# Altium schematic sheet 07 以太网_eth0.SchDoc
size 297 x 209 mm
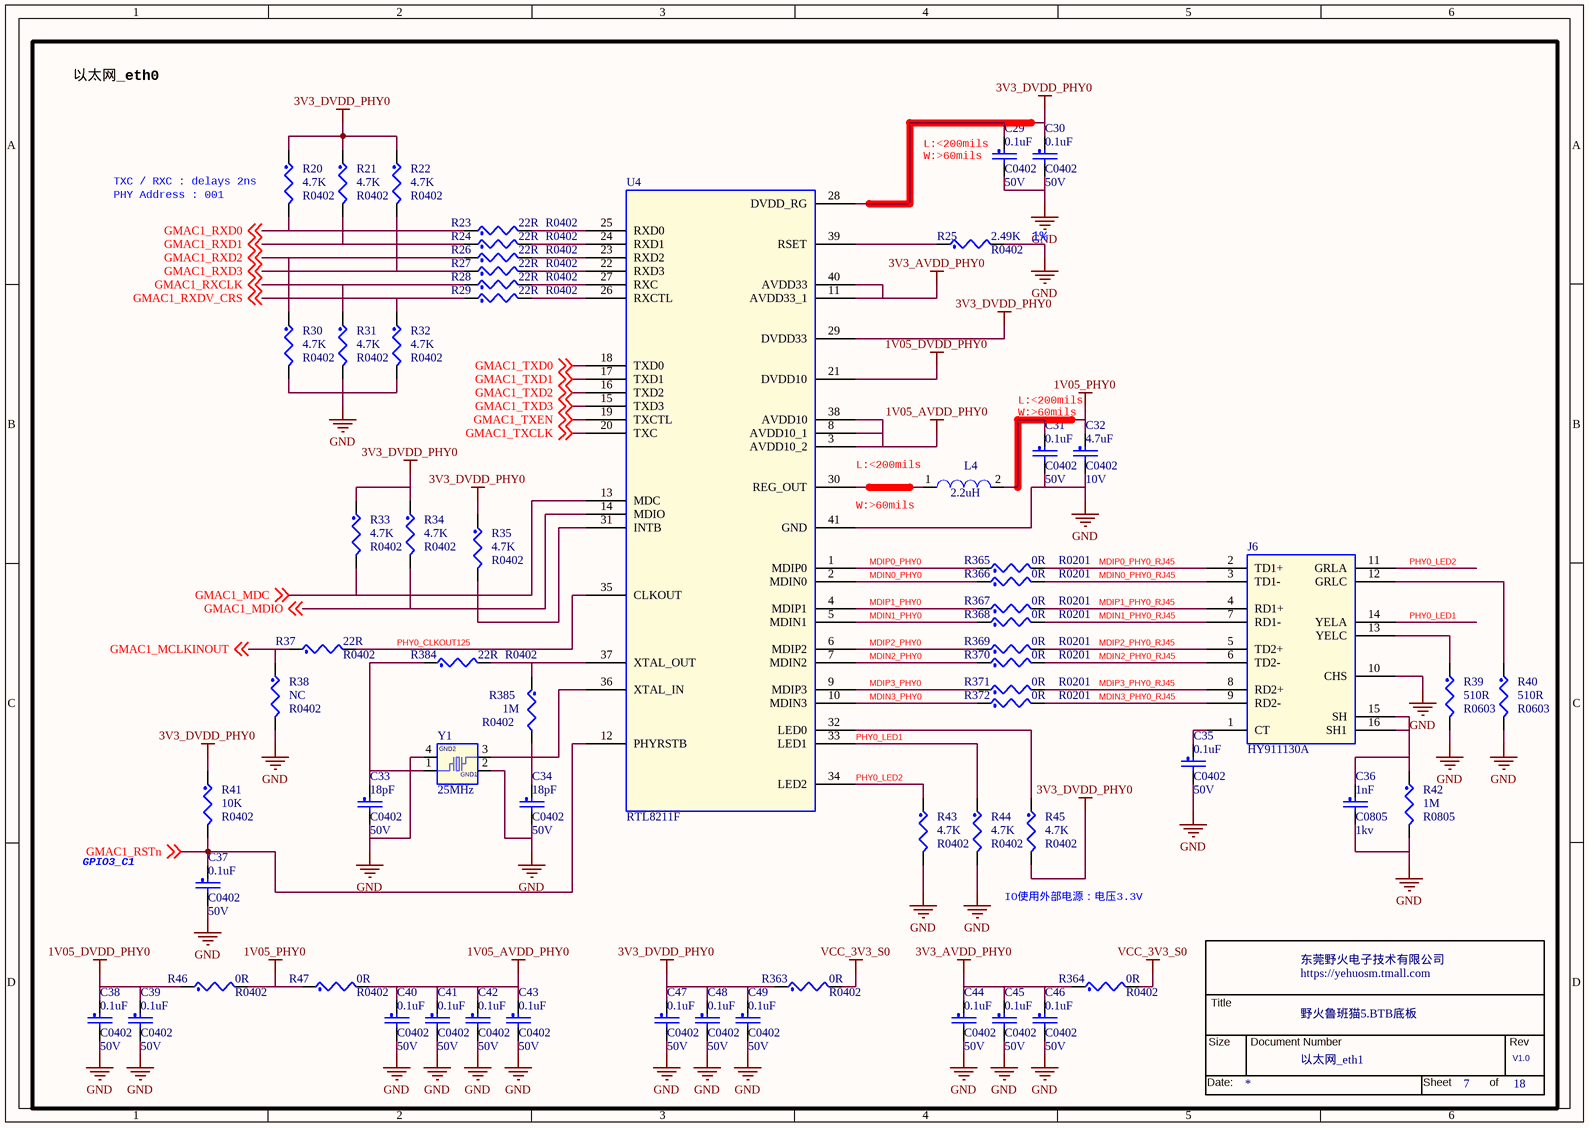
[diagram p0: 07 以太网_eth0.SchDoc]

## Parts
*  Doc: 以太网_eth1  RevCode: V1.0  Title: 野火鲁班猫5.BTB底板  OrgName: 东莞野火电子技术有限公司  Page Number: 7  Page Count: 18  (hidden comment: TitleBlock_YHSCH)  (graphical)
C29  0.1uF  Voltage: 50V  [C0402]
C30  0.1uF  Voltage: 50V  [C0402]
C31  0.1uF  Voltage: 50V  [C0402]
C32  4.7uF  Voltage: 10V  [C0402]
C33  18pF  Voltage: 50V  [C0402]
C34  18pF  Voltage: 50V  [C0402]
C35  0.1uF  Voltage: 50V  [C0402]
C36  1nF  Voltage: 1kv  [C0805]
C37  0.1uF  Voltage: 50V  [C0402]
C38  0.1uF  Voltage: 50V  [C0402]
C39  0.1uF  Voltage: 50V  [C0402]
C40  0.1uF  Voltage: 50V  [C0402]
C41  0.1uF  Voltage: 50V  [C0402]
C42  0.1uF  Voltage: 50V  [C0402]
C43  0.1uF  Voltage: 50V  [C0402]
C44  0.1uF  Voltage: 50V  [C0402]
C45  0.1uF  Voltage: 50V  [C0402]
C46  0.1uF  Voltage: 50V  [C0402]
C47  0.1uF  Voltage: 50V  [C0402]
C48  0.1uF  Voltage: 50V  [C0402]
C49  0.1uF  Voltage: 50V  [C0402]
J6  HY911130A  [HY911130A]
L4  2.2uH  [L2520]
R20  4.7K  [R0402]
R21  4.7K  [R0402]
R22  4.7K  [R0402]
R23  22R  [R0402]
R24  22R  [R0402]
R25  2.49K  [R0402]
R26  22R  [R0402]
R27  22R  [R0402]
R28  22R  [R0402]
R29  22R  [R0402]
R30  4.7K  [R0402]
R31  4.7K  [R0402]
R32  4.7K  [R0402]
R33  4.7K  [R0402]
R34  4.7K  [R0402]
R35  4.7K  [R0402]
R37  22R  [R0402]
R38  NC  [R0402]
R39  510R  [R0603]
R40  510R  [R0603]
R41  10K  [R0402]
R42  1M  [R0805]
R43  4.7K  [R0402]
R44  4.7K  [R0402]
R45  4.7K  [R0402]
R46  0R  [R0402]
R47  0R  [R0402]
R363  0R  [R0402]
R364  0R  [R0402]
R365  0R  [R0201]
R366  0R  [R0201]
R367  0R  [R0201]
R368  0R  [R0201]
R369  0R  [R0201]
R370  0R  [R0201]
R371  0R  [R0201]
R372  0R  [R0201]
R384  22R  [R0402]
R385  1M  [R0402]
U4  RTL8211F  [qfp_40p_r]
Y1  25MHz  [3225]

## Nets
1V05_AVDD_PHY0: C40.1 C41.1 C42.1 C43.1 R47.2 U4.3(AVDD10_2) U4.8(AVDD10_1) U4.38(AVDD10)
1V05_DVDD_PHY0: C38.1 C39.1 R46.1 U4.21(DVDD10)
1V05_PHY0: C31.1 C32.1 L4.2 R46.2 R47.1
3V3_AVDD_PHY0: C44.1 C45.1 C46.1 R364.1 U4.11(AVDD33_1) U4.40(AVDD33)
3V3_DVDD_PHY0: C29.1 C30.1 C47.1 C48.1 C49.1 R20.1 R21.1 R22.1 R33.1 R34.1 R35.1 R41.1 R45.2 R363.1 U4.28(DVDD_RG) U4.29(DVDD33)
GND: C29.2 C30.2 C31.2 C32.2 C33.2 C34.2 C35.2 C36.2 C37.2 C38.2 C39.2 C40.2 C41.2 C42.2 C43.2 C44.2 C45.2 C46.2 C47.2 C48.2 C49.2 J6.10(CHS) R25.2 R30.2 R31.2 R32.2 R38.2 R39.2 R40.2 R42.2 R43.2 R44.2 U4.41(GND) Y1.2(GND1) Y1.4(GND2)
VCC_3V3_S0: R363.2 R364.2
GMAC1_MCLKINOUT: R37.1 R38.1 ; off-sheet GMAC1_MCLKINOUT
GMAC1_MDC: R33.2 U4.13(MDC) ; off-sheet GMAC1_MDC
GMAC1_MDIO: R34.2 U4.14(MDIO) ; off-sheet GMAC1_MDIO
GMAC1_RSTn: C37.1 R41.2 U4.12(PHYRSTB) ; off-sheet GMAC1_RSTn
GMAC1_RXCLK: R28.1 R31.1 ; off-sheet GMAC1_RXCLK
GMAC1_RXD0: R20.2 R23.1 ; off-sheet GMAC1_RXD0
GMAC1_RXD1: R21.2 R24.1 ; off-sheet GMAC1_RXD1
GMAC1_RXD2: R26.1 R30.1 ; off-sheet GMAC1_RXD2
GMAC1_RXD3: R22.2 R27.1 ; off-sheet GMAC1_RXD3
GMAC1_RXDV_CRS: R29.1 R32.1 ; off-sheet GMAC1_RXDV_CRS
GMAC1_TXCLK: U4.20(TXC) ; off-sheet GMAC1_TXCLK
GMAC1_TXD0: U4.18(TXD0) ; off-sheet GMAC1_TXD0
GMAC1_TXD1: U4.17(TXD1) ; off-sheet GMAC1_TXD1
GMAC1_TXD2: U4.16(TXD2) ; off-sheet GMAC1_TXD2
GMAC1_TXD3: U4.15(TXD3) ; off-sheet GMAC1_TXD3
GMAC1_TXEN: U4.19(TXCTL) ; off-sheet GMAC1_TXEN
MDIN0_PHY0: R366.1 U4.2(MDIN0)
MDIN0_PHY0_RJ45: J6.3(TD1-) R366.2
MDIN1_PHY0: R368.1 U4.5(MDIN1)
MDIN1_PHY0_RJ45: J6.7(RD1-) R368.2
MDIN2_PHY0: R370.1 U4.7(MDIN2)
MDIN2_PHY0_RJ45: J6.6(TD2-) R370.2
MDIN3_PHY0: R372.1 U4.10(MDIN3)
MDIN3_PHY0_RJ45: J6.9(RD2-) R372.2
MDIP0_PHY0: R365.1 U4.1(MDIP0)
MDIP0_PHY0_RJ45: J6.2(TD1+) R365.2
MDIP1_PHY0: R367.1 U4.4(MDIP1)
MDIP1_PHY0_RJ45: J6.4(RD1+) R367.2
MDIP2_PHY0: R369.1 U4.6(MDIP2)
MDIP2_PHY0_RJ45: J6.5(TD2+) R369.2
MDIP3_PHY0: R371.1 U4.9(MDIP3)
MDIP3_PHY0_RJ45: J6.8(RD2+) R371.2
PHY0_CLKOUT125: R37.2 U4.35(CLKOUT)
PHY0_LED1: J6.14(YELA) R44.1 U4.33(LED1)
PHY0_LED2: J6.11(GRLA) R43.1 U4.34(LED2)
NetC33_1: C33.1 R384.1 Y1.1
NetC34_1: C34.1 R385.2
NetC35_1: C35.1 J6.1(CT)
NetC36_1: C36.1 J6.15(SH) J6.16(SH1) R42.1
NetJ6_12: J6.12(GRLC) R40.1
NetJ6_13: J6.13(YELC) R39.1
NetL4_1: L4.1 U4.30(REG_OUT)
NetR23_2: R23.2 U4.25(RXD0)
NetR24_2: R24.2 U4.24(RXD1)
NetR25_1: R25.1 U4.39(RSET)
NetR26_2: R26.2 U4.23(RXD2)
NetR27_2: R27.2 U4.22(RXD3)
NetR28_2: R28.2 U4.27(RXC)
NetR29_2: R29.2 U4.26(RXCTL)
NetR35_2: R35.2 U4.31(INTB)
NetR45_1: R45.1 U4.32(LED0)
NetR384_2: R384.2 R385.1 U4.37(XTAL_OUT)
NetU4_36: U4.36(XTAL_IN) Y1.3

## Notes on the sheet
- 以太网_eth0
- (near C29) L:<200mils
  W:>60mils
- PHY Address : 001
- TXC / RXC : delays 2ns
- (near R25) 1%
- L:<200mils
  W:>60mils
- L:<200mils
- W:>60mils
- GPIO3_C1
- IO使用外部电源：电压3.3V

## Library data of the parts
* = TitleBlock_YHSCH: Cage Code: 1
C29-C31 C35 C37-C43 C47-C49 = CAP_NP: CLASS: DISCRETE; 规格: 贴片电容0.1uF 10% 50V X5R 0402; 规格编号: 0402X104K500NT; 条码: EBF29060118; 品牌: 风华; 类别: 贴片电容0402; 规格书: 风华电容.pdf; 价格: 0.029826; 生命周期: 量产
C32 = CAP_NP: CLASS: DISCRETE; 规格: 贴片电容4.7uF 10% 10V X5R 0402; 规格编号: CC0402KRX5R6BB475; 条码: EBF29060248; 品牌: 国巨; 类别: 贴片电容0402; 规格书: 国巨-贴片电容.pdf; 价格: 0.059058; 生命周期: 量产
C33 C34 = CAP_NP: CLASS: DISCRETE; 生命周期: 量产; 价格: 0.00515; 规格书: 风华电容.pdf; 类别: 贴片电容0402; 品牌: 风华; 条码: EBF29060235; 规格编号: 0402CG180J500NT; 规格: 贴片电容18pF 5% 50V C0G 0402
C36 = CAP_NP: CLASS: DISCRETE; 规格: 贴片电容1nF 10% 1kV X7R 0805; 规格编号: 0805B102K102CT; 条码: EBF29060304; 品牌: 华新科; 类别: 贴片电容0805; 规格书: 华新科0805系列高压贴片电容.pdf; 价格: 0.083527; 生命周期: 量产
C44-C46 = CAP_NP: CLASS: DISCRETE; 生命周期: 量产; 价格: 0.029826; 规格书: 风华电容.pdf; 类别: 贴片电容0402; 品牌: 风华; 条码: EBF29060118; 规格编号: 0402X104K500NT; 规格: 贴片电容0.1uF 10% 50V X5R 0402
J6 = HY911130A: 可替代料: EBF29040053; 生命周期: 量产; 价格: 11.12; 规格书: 汉仁_1000M_ HY911130A.pdf; 类别: 网口; 品牌: 汉仁; 规格: 屏蔽式以太网连接器RJ45 引脚数14 LED灯黄绿 1000M
L4 = IND: CLASS: DISCRETE; 规格: 功率电感2.2uH 2.2uH ±20% 2.06A 85mΩ; 规格编号: WIP252012P-2R2ML; 条码: EBFCIS220927171910; 品牌: 佳邦; 类别: 贴片电感2520; 规格书: 佳邦_ WIP252012P-2R2ML.pdf; 价格: 0.129914; 生命周期: 量产
R20-R22 R30-R35 = RES: CLASS: DISCRETE; 规格: 贴片电阻4.7K 1% 1/16W 0402; 规格编号: RI0402L4701FT; 条码: EBF29070047; 品牌: 合科泰; 类别: 贴片电阻0402; 规格书: 合科泰-RI系列电阻.pdf; 生命周期: 量产
R23 R24 R26-R29 R37 R384 = RES: CLASS: DISCRETE; 生命周期: 量产; 规格书: 合科泰-RI系列电阻.pdf; 类别: 贴片电阻0402; 品牌: 合科泰; 条码: EBF29070181; 规格编号: RI0402L22R0FT; 规格: 贴片电阻22R 1% 1/16W 0402
R25 = RES: CLASS: DISCRETE; 价格: 0.004709; 生命周期: 量产; 规格书: 厚声-无铅厚膜电阻.pdf; 类别: 贴片电阻0402; 品牌: 厚声; 条码: EBF29070292; 规格编号: 0402WGF2491TCE; 规格: 贴片电阻2.49K 1% 1/16W 0402
R38 = RES: CLASS: DISCRETE; 规格: 贴片电阻NC 预留; 条码: EBF29070087; 类别: 贴片电阻0402
R39 R40 = RES: CLASS: DISCRETE; 规格: 贴片电阻510R 1% 1/10W 0603; 规格编号: RI0603L5100FT; 条码: EBF29070091; 品牌: 合科泰; 类别: 贴片电阻0603; 规格书: 合科泰-RI系列电阻.pdf; 生命周期: 量产
R41 = RES: CLASS: DISCRETE; 规格: 贴片电阻10K 1% 1/16W 0402; 规格编号: 0402WGF1002TCE; 条码: EBF29070046; 品牌: 厚声; 类别: 贴片电阻0402; 规格书: 厚声-无铅厚膜电阻.pdf; 价格: 0.002773; 生命周期: 量产
R42 = RES: CLASS: DISCRETE; 生命周期: 量产; 价格: 0.02396; 规格书: YAGEO国巨厚膜无铅电阻.pdf; 类别: 贴片电阻0805; 品牌: 国巨; 条码: EBF29070294; 规格编号: AC0805FR-071ML; 规格: 贴片电阻1M 1% 1/8W 0805
R43-R45 = RES: CLASS: DISCRETE; 生命周期: 量产; 规格书: 合科泰-RI系列电阻.pdf; 类别: 贴片电阻0402; 品牌: 合科泰; 条码: EBF29070047; 规格编号: RI0402L4701FT; 规格: 贴片电阻4.7K 1% 1/16W 0402
R46 R47 R364 = RES: CLASS: DISCRETE; 规格: 贴片电阻0R 1% 1/16W 0402; 规格编号: RI0402L000FT; 条码: EBF29070049; 品牌: 合科泰; 类别: 贴片电阻0402; 规格书: 合科泰-RI系列电阻.pdf; 生命周期: 量产
R363 = RES: CLASS: DISCRETE; 生命周期: 量产; 规格书: 合科泰-RI系列电阻.pdf; 类别: 贴片电阻0402; 品牌: 合科泰; 条码: EBF29070049; 规格编号: RI0402L000FT; 规格: 贴片电阻0R 1% 1/16W 0402
R365-R372 = RES: CLASS: DISCRETE; 规格: 贴片电阻0R 1% 1/20W 0201; 规格编号: RI0201L0000FT; 条码: EBF29070164; 品牌: 合科泰; 类别: 贴片电阻0201; 规格书: 合科泰-RI系列电阻.pdf; 生命周期: 量产
R385 = RES: CLASS: DISCRETE; 规格: 贴片电阻1M 1% 1/16W 0402; 规格编号: RI0402L1004FT; 条码: EBF29070062; 品牌: 厚声; 类别: 贴片电阻0402; 规格书: 合科泰-RI系列电阻.pdf; 生命周期: 量产
U4 = RTL8211F: 价格: 15.2; 生命周期: 量产; 规格书: 瑞昱_RTL8211F-CG.pdf; 类别: 以太网芯片; 品牌: 瑞昱; 条码: EBF29150018; 规格编号: RTL8211F-CG; 规格: 以太网芯片 10M/100M/1000M 控制接口：RGMII RGMII电压：3.3V/2.5V/1.8V/1.5V
Y1 = CRYSTAL_4P: CLASS: IC; 生命周期: 量产; 价格: 0.385846; 规格书: 扬兴科技-25MHZ.pdf; 类别: 贴片晶振 3225; 品牌: 扬兴科技; 条码: EBF29100005; 规格编号: X322525MQB4SI; 规格: 无源晶振25MHZ 50Ω 16pF 3225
